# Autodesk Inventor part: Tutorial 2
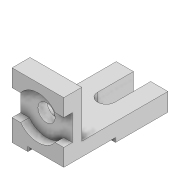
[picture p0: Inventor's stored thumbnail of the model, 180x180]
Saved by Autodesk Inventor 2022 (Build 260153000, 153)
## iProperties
Created: 2021-03
Part Number: Tutorial 2
Material: Generic
Document SubType Name: Modeling
Designer: ASUS Laptop
Density: 1 g/cm^3
Appearance: Default
Author: ASUS Laptop
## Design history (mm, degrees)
sketch "Sketch1"
  geometry: L1 (0, 0)-(90, 0); L2 (90, 0)-(90, -25); L3 (90, -25)-(25, -25); L4 (25, -25)-(25, -145); L5 (25, -145)-(0, -145); L6 (0, -145)-(0, 0)
  constraints: 12 end point, 6 perpendicular, 1 horizontal
  dimensions: "d0" = 145 distance of L5.end L1.start; "d1" = 90 distance between parallel lines of L2 L6; "d2" = 25 distance of L1.end L2.end
extrude "Extrusion1" new body sketch "Sketch1" stored distance "d4" = 72; taper "d5" = 0 deg
sketch "Sketch2"
  geometry: L1 (0, 0)-(72, 0); L2 (72, 0)-(72, 6); L3 (72, 6)-(0, 6); L4 (0, 6)-(0, 0)
  constraints: 8 end point, 2 parallel, 1 horizontal, 1 perpendicular
  dimensions: "d6" = 72 distance of L1.start L1.end; "d7" = 6 distance between parallel lines of L1 L3
extrude "Extrusion2" cut sketch "Sketch2" distance "d8" = 50; taper "d9" = 0 deg
sketch "Sketch3"
  geometry: L1 (12, -24)-(0, -24); L2 (0, -90)-(0, 0) reference; L3 (0, -24)-(0, -60); L4 (0, -60)-(12, -60); L5 (60, -24)-(72, -24); L6 (72, 0)-(72, -84) reference; L7 (72, -24)-(72, -60); L8 (72, -60)-(60, -60); L9 (72, -90)-(22, -90) reference; L10 (0, -90)-(22, -90) reference; A1 r 30 centre (36, -42) between (12, -60) and (60, -60); A2 r 30 centre (36, -42) between (60, -24) and (12, -24); 3 further points
  constraints: 12 end point, 4 point on circle, 4 point on line, 2 centre point, 2 perpendicular, 1 collinear, 1 concentric, 1 horizontal, 1 parallel, 1 vertical
  dimensions: "d10" = 30 radius of A2; "d11" = 36 distance from line of A1.centre L2; "d12" = 48 distance from line of L9 A1.centre; "d13" = 30 distance between parallel lines of L4 L10; "d14" = 36 distance between parallel lines of L4 L1
extrude "Extrusion3" cut sketch "Sketch3" distance "d15" = 12; taper "d16" = 0 deg
sketch "Sketch4"
  geometry: C1 r 12 at (36, -42); A1 r 30 centre (36, -42) between (60, -24) and (12, -24) reference; 1 further point
  constraints: 1 centre point, 1 concentric
  dimensions: "d17" = 24 diameter of C1
extrude "Extrusion4" cut sketch "Sketch4" extent not by distance; stored distance "d18" = 10; taper "d19" = 0 deg
sketch "Sketch5"
  geometry: L1 (24, 120)-(24, 70); L2 (48, 70)-(48, 120); L3 (48, 120)-(24, 120); L4 (72, 120)-(72, 0) reference; A1 r 12 centre (36, 70) between (24, 70) and (48, 70); 2 further points
  constraints: 6 end point, 2 point on circle, 2 tangent, 1 centre point, 1 parallel, 1 perpendicular, 1 point on line, 1 vertical
  dimensions: "d20" = 36 distance from line of A1.centre L4; "d21" = 12 radius of A1; "d22" = 50 distance of L2.start L2.end
extrude "Extrusion5" cut sketch "Sketch5" extent not by distance; stored distance "d23" = 0; taper "d24" = 0 deg
body "Solid1"
